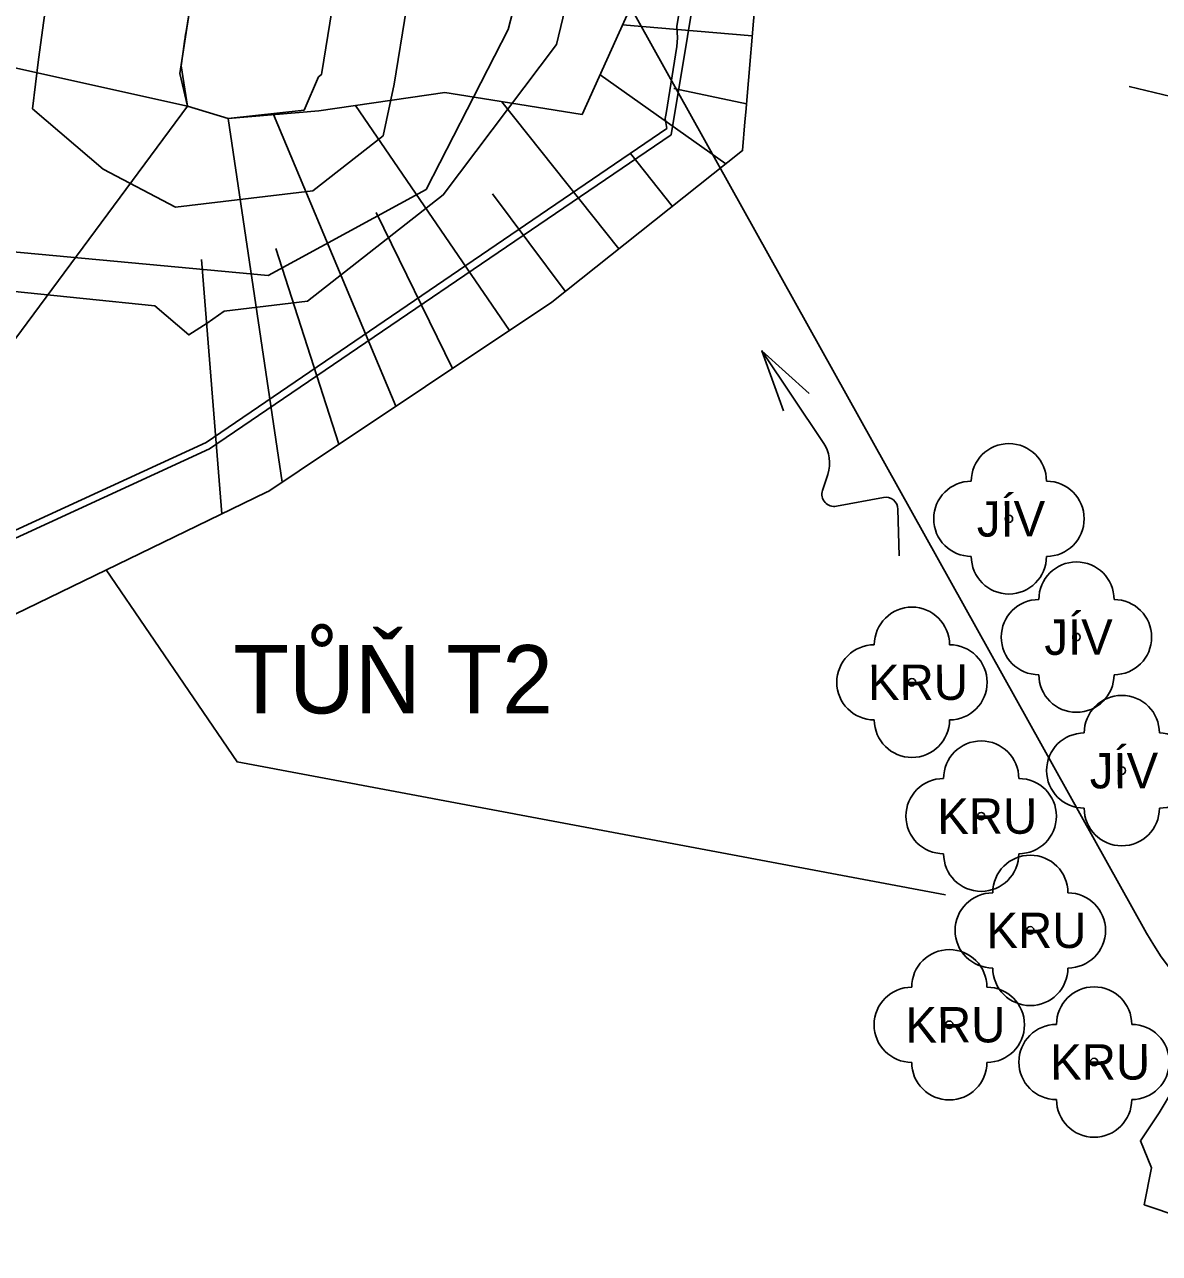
# Model space of a CAD drawing. Extents: x -564037 to -563722, y -1163561 to -1163412.
# Drawn here: x -563924.44 to -563903.68, y -1163510.15 to -1163487.66 of the extents above; entities that cross this region are included whole.
import ezdxf

# ---------------------------------------------------------------- set-up
doc = ezdxf.new("R2010")
doc.units = 0
for name, color, linetype in [('4', 7, 'Continuous'), ('5', 7, 'Continuous'), ('Default', 7, 'Continuous'), ('Line', 7, 'Continuous'), ('podélný profil', 7, 'Continuous'), ('Vrstva 1', 7, 'Continuous'), ('Vrstva 2', 7, 'Continuous')]:
    doc.layers.add(name, color=color, linetype=linetype)

msp = doc.modelspace()

# ---------------------------------------------------------------- linework, layer by layer
for points in [[(-563930.469, -1163501.126), (-563927.863, -1163499.14), (-563925.937, -1163497.674), (-563921.059, -1163495.43), (-563912.613, -1163489.681), (-563911.421, -1163482.517), (-563913.266, -1163479.715), (-563914.137, -1163478.749), (-563916.309, -1163476.467), (-563917.281, -1163475.995), (-563923.761, -1163471.506), (-563924, -1163472.797), (-563925.435, -1163477.844), (-563927.008, -1163483.992), (-563927.659, -1163487.507), (-563928.13, -1163490.05), (-563928.806, -1163493.379), (-563930.34, -1163499.841), (-563930.622, -1163501.15)], [(-563915.586, -1163481.384), (-563914.537, -1163483.686), (-563915.595, -1163487.753), (-563917.092, -1163490.681), (-563919.984, -1163492.255), (-563925.31, -1163491.764), (-563926.027, -1163491.364), (-563926.218, -1163490.597), (-563925.375, -1163485.285), (-563924.678, -1163482.734), (-563924.029, -1163478.524), (-563922.899, -1163477.259), (-563919.326, -1163477.602), (-563916.674, -1163478.991)]]:
    msp.add_lwpolyline(points, close=True)
for points in [[(-563917.911, -1163481.802), (-563919.001, -1163488.543), (-563919.009, -1163488.581), (-563919.062, -1163488.623), (-563919.326, -1163489.233), (-563920.716, -1163489.381), (-563921.461, -1163489.159), (-563921.575, -1163488.419), (-563921.52, -1163488.022), (-563921.519, -1163488.013), (-563921.518, -1163488.005), (-563921.517, -1163487.995), (-563921.516, -1163487.988), (-563921.515, -1163487.978), (-563921.514, -1163487.974), (-563921.514, -1163487.97), (-563921.514, -1163487.97), (-563921.511, -1163487.953), (-563921.508, -1163487.937), (-563921.508, -1163487.935), (-563921.505, -1163487.919), (-563921.504, -1163487.912), (-563921.503, -1163487.901), (-563921.501, -1163487.884), (-563921.498, -1163487.865), (-563921.497, -1163487.859), (-563921.496, -1163487.847), (-563921.493, -1163487.828), (-563920.465, -1163481.469)], [(-563927.306, -1163492.273), (-563922.057, -1163492.813), (-563921.435, -1163493.345), (-563921.102, -1163493.131), (-563920.787, -1163492.909), (-563919.265, -1163492.727), (-563916.779, -1163490.783), (-563914.71, -1163488.029), (-563913.607, -1163483.439)], [(-563925.993, -1163497.549), (-563921.117, -1163495.312), (-563912.692, -1163489.565), (-563912.719, -1163489.382), (-563912.7, -1163489.29), (-563912.508, -1163488.065), (-563912.499, -1163487.988), (-563912.497, -1163487.906), (-563912.506, -1163487.699), (-563911.986, -1163484.484)], [(-563921.157, -1163485.676), (-563921.598, -1163488.562), (-563921.461, -1163489.159), (-563920.716, -1163489.381), (-563919.058, -1163489.245), (-563919.058, -1163489.245), (-563919.058, -1163489.245), (-563916.75, -1163488.907), (-563916.212, -1163488.994), (-563914.24, -1163489.313), (-563912.713, -1163485.924)], [(-563917.23, -1163485.969), (-563917.681, -1163488.756), (-563917.877, -1163489.7), (-563919.165, -1163490.707), (-563921.676, -1163491.008), (-563923.002, -1163490.31), (-563924.293, -1163489.206), (-563924.187, -1163488.301), (-563923.991, -1163486.868)], [(-563907.591, -1163503.589), (-563920.552, -1163501.157), (-563922.95, -1163497.645)], [(-563901.311, -1163510.152), (-563903.956, -1163509.261), (-563903.825, -1163508.585), (-563904.027, -1163508.089), (-563903.682, -1163507.578), (-563903.161, -1163506.698), (-563902.64, -1163505.818), (-563902.226, -1163504.902)]]:
    msp.add_lwpolyline(points)
at = {"layer": '5'}
for p, q in [((-563921.324, -1163473.035), (-563903.913, -1163504.291)), ((-563904.23, -1163488.796), (-563873.359, -1163496.24))]:
    msp.add_line(p, q, dxfattribs=at)
msp.add_arc((-563899.545, -1163501.858), 5, 209.1194, 298.6163, dxfattribs=at)
at = {"layer": 'Default'}
msp.add_lwpolyline([(-563925.948, -1163485.244), (-563926.867, -1163489.1), (-563927.916, -1163493.212), (-563928.032, -1163493.665), (-563928.034, -1163493.674), (-563928.134, -1163494.067), (-563928.211, -1163494.367), (-563929.345, -1163497.668), (-563930.401, -1163500.745), (-563930.002, -1163500.645), (-563928.239, -1163500.208), (-563925.246, -1163498.757), (-563920.654, -1163496.532), (-563920.013, -1163496.222), (-563919.971, -1163496.201), (-563919.419, -1163495.832), (-563914.794, -1163492.742), (-563911.305, -1163489.972), (-563911.26, -1163489.446), (-563911.245, -1163489.265), (-563911.055, -1163487.019)], dxfattribs=at)
at = {"layer": 'Line'}
for p, q in [((-563911.127, -1163487.869), (-563913.499, -1163487.668)), ((-563926.609, -1163488.017), (-563921.461, -1163489.159)), ((-563911.61, -1163490.214), (-563913.912, -1163488.587)), ((-563912.565, -1163488.834), (-563911.232, -1163489.114)), ((-563921.461, -1163489.159), (-563929.957, -1163500.634)), ((-563915.571, -1163493.261), (-563918.383, -1163489.146)), ((-563913.568, -1163491.769), (-563915.706, -1163489.076)), ((-563919.728, -1163496.039), (-563920.716, -1163489.381)), ((-563917.65, -1163494.65), (-563919.887, -1163489.313)), ((-563913.357, -1163490.024), (-563912.589, -1163490.991)), ((-563915.878, -1163490.76), (-563914.547, -1163492.546)), ((-563918.005, -1163491.102), (-563916.61, -1163493.956)), ((-563921.206, -1163491.965), (-563920.833, -1163496.619)), ((-563919.844, -1163491.761), (-563918.689, -1163495.344))]:
    msp.add_line(p, q, dxfattribs=at)
at = {"layer": 'podélný profil'}
for points in [[(-563910.557, -1163494.73), (-563910.951, -1163493.635), (-563910.088, -1163494.416)], [(-563910.951, -1163493.635), (-563909.828, -1163495.311)], [(-563909.746, -1163495.896), (-563909.841, -1163496.188)], [(-563909.584, -1163496.479), (-563908.729, -1163496.319)], [(-563908.462, -1163496.534), (-563908.439, -1163497.385)]]:
    msp.add_lwpolyline(points, dxfattribs=at)
for centre, radius, start, end in [((-563910.391, -1163495.688), 0.677, 342.1284, 33.8229), ((-563909.626, -1163496.258), 0.226, 162.1305, 280.6775), ((-563908.687, -1163496.54), 0.226, 1.534, 100.6512)]:
    msp.add_arc(centre, radius, start, end, dxfattribs=at)
at = {"layer": 'Vrstva 2'}
for centre in [(-563906.432, -1163496.709), (-563905.196, -1163498.874), (-563908.206, -1163499.701), (-563904.366, -1163501.316), (-563906.939, -1163502.15), (-563906.04, -1163504.241), (-563907.522, -1163505.968), (-563904.873, -1163506.649)]:
    msp.add_circle(centre, 0.0688, dxfattribs=at)
for centre, start, end in [((-563906.432, -1163496.021), 0, 180), ((-563907.12, -1163496.709), 90, 270), ((-563905.744, -1163496.709), 270, 90), ((-563906.432, -1163497.397), 180, 0), ((-563905.196, -1163498.186), 0, 180), ((-563905.884, -1163498.874), 90, 270), ((-563904.508, -1163498.874), 270, 90), ((-563908.206, -1163499.013), 0, 180), ((-563908.894, -1163499.701), 90, 270), ((-563907.518, -1163499.701), 270, 90), ((-563905.196, -1163499.562), 180, 0), ((-563904.366, -1163500.628), 0, 180), ((-563908.206, -1163500.388), 180, 0), ((-563905.054, -1163501.316), 90, 270), ((-563903.678, -1163501.316), 270, 90), ((-563906.939, -1163501.462), 0, 180), ((-563907.627, -1163502.15), 90, 270), ((-563906.251, -1163502.15), 270, 90), ((-563904.366, -1163502.004), 180, 0), ((-563906.939, -1163502.838), 180, 0), ((-563906.04, -1163503.553), 0, 180), ((-563906.728, -1163504.241), 90, 270), ((-563905.352, -1163504.241), 270, 90), ((-563907.522, -1163505.28), 0, 180), ((-563906.04, -1163504.929), 180, 0), ((-563908.21, -1163505.968), 90, 270), ((-563906.834, -1163505.968), 270, 90), ((-563904.873, -1163505.961), 0, 180), ((-563905.561, -1163506.649), 90, 270), ((-563904.185, -1163506.649), 270, 90), ((-563907.522, -1163506.656), 180, 0), ((-563904.873, -1163507.337), 180, 0)]:
    msp.add_arc(centre, 0.688, start, end, dxfattribs=at)

# ---------------------------------------------------------------- texts
at = {"layer": '4'}
msp.add_text('TŮŇ T2', height=1.25, rotation=360, dxfattribs=at).set_placement((-563920.624, -1163500.27))
at = {"layer": 'Vrstva 1'}
for s, p in [('JÍV', (-563907.018, -1163497.035)), ('JÍV', (-563905.782, -1163499.199)), ('KRU', (-563909.009, -1163500.027)), ('JÍV', (-563904.952, -1163501.642)), ('KRU', (-563907.742, -1163502.476)), ('KRU', (-563906.842, -1163504.567)), ('KRU', (-563908.325, -1163506.294)), ('KRU', (-563905.676, -1163506.975))]:
    msp.add_text(s, height=0.648, rotation=0.1546, dxfattribs=at).set_placement(p)

doc.saveas('drawing.dxf')
